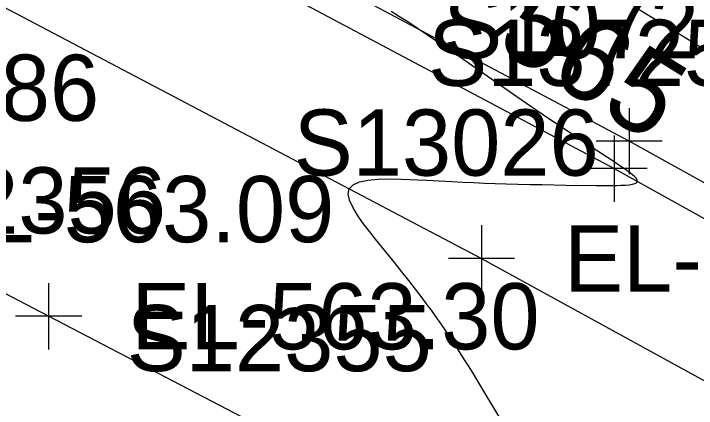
# Model space of a CAD drawing. Extents: x 1729869 to 1735532, y 648588 to 653771.
# Drawn here: x 1730620.93 to 1730662.21, y 652456.64 to 652480.48 of the extents above; entities that cross this region are included whole.
import ezdxf

# ---------------------------------------------------------------- set-up
doc = ezdxf.new("R2010")
doc.units = 0
for name, color, linetype in [('SURVEY - CONTOURS - Index with Text', 7, 'Continuous'), ('SURVEY - CONTOURS - Intermediate with optional Text', 7, 'Continuous'), ('SURVEY - DTM - Breaklines', 7, 'Continuous'), ('SURVEY - DTM - Breaklines - Points - Locators', 7, 'Continuous'), ('SURVEY - DTM - Breaklines - Points - Numbers', 7, 'Continuous'), ('SURVEY - TRANSPORTATION - Features', 7, 'Continuous'), ('SURVEY - TRANSPORTATION - Features - Points - Locators', 7, 'Continuous'), ('SURVEY - TRANSPORTATION - Features - Points - Numbers', 7, 'Continuous'), ('SURVEY - TRANSPORTATION - Roads', 7, 'Continuous'), ('SURVEY - TRANSPORTATION - Roads - Points - Elevations', 7, 'Continuous'), ('SURVEY - TRANSPORTATION - Roads - Points - Locators', 7, 'Continuous'), ('SURVEY - TRANSPORTATION - Roads - Points - Numbers', 7, 'Continuous')]:
    doc.layers.add(name, color=color, linetype=linetype)

msp = doc.modelspace()

# ---------------------------------------------------------------- linework, layer by layer
at = {"layer": 'SURVEY - CONTOURS - Intermediate with optional Text'}
for points in [[(1730662.688, 652478.32), (1730661.729, 652478.912), (1730660.479, 652479.674), (1730658.654, 652480.775)], [(1730652.709, 652452.13), (1730649.387, 652457.631), (1730648.728, 652458.714), (1730648.466, 652459.138), (1730648.201, 652459.563), (1730647.932, 652459.989), (1730647.659, 652460.415), (1730647.381, 652460.841), (1730647.06, 652461.322), (1730646.721, 652461.815), (1730646.547, 652462.063), (1730646.37, 652462.313), (1730646.189, 652462.564), (1730646.003, 652462.818), (1730645.626, 652463.321), (1730645.233, 652463.835), (1730644.826, 652464.358), (1730644.407, 652464.887), (1730643.978, 652465.422), (1730642.82, 652466.849), (1730642.467, 652467.293), (1730642.072, 652467.81), (1730641.719, 652468.311), (1730641.433, 652468.784), (1730641.238, 652469.215), (1730641.159, 652469.592), (1730641.22, 652469.902), (1730641.453, 652470.147), (1730641.84, 652470.316), (1730642.353, 652470.422), (1730642.963, 652470.477), (1730643.644, 652470.494), (1730644.368, 652470.484), (1730644.87, 652470.468), (1730645.377, 652470.448), (1730645.887, 652470.423), (1730647.426, 652470.341), (1730648.089, 652470.308), (1730648.748, 652470.278), (1730649.404, 652470.251), (1730650.056, 652470.227), (1730650.707, 652470.206), (1730651.42, 652470.185), (1730652.162, 652470.167), (1730652.895, 652470.152), (1730654.31, 652470.13), (1730656.161, 652470.108), (1730656.909, 652470.104), (1730657.402, 652470.108), (1730657.649, 652470.113), (1730657.912, 652470.125), (1730658.144, 652470.144), (1730658.34, 652470.172), (1730658.494, 652470.212), (1730658.598, 652470.266), (1730658.647, 652470.336), (1730658.639, 652470.419), (1730658.582, 652470.517), (1730658.481, 652470.628), (1730658.345, 652470.75), (1730658.178, 652470.881), (1730657.93, 652471.061), (1730657.652, 652471.253), (1730657.178, 652471.57), (1730655.476, 652472.685), (1730654.462, 652473.355), (1730653.416, 652474.054), (1730652.519, 652474.66), (1730651.625, 652475.271), (1730650.376, 652476.135), (1730647.478, 652478.152), (1730646.936, 652478.526), (1730646.408, 652478.889), (1730645.898, 652479.234), (1730645.415, 652479.557), (1730645.248, 652479.667), (1730644.762, 652479.983), (1730644.271, 652480.297), (1730643.764, 652480.617)]]:
    msp.add_lwpolyline(points, dxfattribs=at)
at = {"layer": 'SURVEY - DTM - Breaklines'}
msp.add_lwpolyline([(1730701.831, 652448.311), (1730680.069, 652460.611), (1730658.147, 652472.777), (1730635.92, 652484.613), (1730613.644, 652496.246), (1730591.357, 652507.57), (1730568.855, 652518.695), (1730546.07, 652529.531), (1730523.318, 652540.081), (1730500.602, 652550.622), (1730482.95, 652558.576)], dxfattribs=at)
at = {"layer": 'SURVEY - DTM - Breaklines - Points - Locators'}
for p, q in [((1730658.147, 652474.777), (1730658.147, 652470.777)), ((1730660.147, 652472.777), (1730656.147, 652472.777))]:
    msp.add_line(p, q, dxfattribs=at)
at = {"layer": 'SURVEY - TRANSPORTATION - Features'}
msp.add_lwpolyline([(1730482.128, 652556.778), (1730499.818, 652548.902), (1730522.526, 652538.364), (1730545.264, 652527.819), (1730568.012, 652517.002), (1730590.497, 652505.885), (1730612.785, 652494.561), (1730635.04, 652482.939), (1730657.237, 652471.119), (1730679.148, 652458.959), (1730700.909, 652446.658)], dxfattribs=at)
at = {"layer": 'SURVEY - TRANSPORTATION - Features - Points - Locators'}
for p, q in [((1730657.237, 652473.119), (1730657.237, 652469.119)), ((1730659.237, 652471.119), (1730655.237, 652471.119))]:
    msp.add_line(p, q, dxfattribs=at)
at = {"layer": 'SURVEY - TRANSPORTATION - Roads'}
for points in [[(1730477.741, 652549.555), (1730480.41, 652548.336), (1730500.427, 652539.207), (1730529.488, 652525.811), (1730560.256, 652511.345), (1730583.532, 652499.762), (1730613.819, 652484.316), (1730649.217, 652465.696), (1730673.763, 652452.23)], [(1730639.01, 652453.881), (1730623.049, 652462.2), (1730610.635, 652468.672), (1730596.418, 652476.006), (1730574.978, 652486.792), (1730557.081, 652495.716), (1730531.873, 652507.902), (1730522.838, 652512.189), (1730497.394, 652523.874), (1730478.726, 652532.248)]]:
    msp.add_lwpolyline(points, dxfattribs=at)
at = {"layer": 'SURVEY - TRANSPORTATION - Roads - Points - Locators'}
for p, q in [((1730649.217, 652467.696), (1730649.217, 652463.696)), ((1730651.217, 652465.696), (1730647.217, 652465.696)), ((1730623.049, 652464.2), (1730623.049, 652460.2)), ((1730625.049, 652462.2), (1730621.049, 652462.2))]:
    msp.add_line(p, q, dxfattribs=at)

# ---------------------------------------------------------------- texts
at = {"layer": 'SURVEY - CONTOURS - Index with Text'}
msp.add_text('565', height=5, rotation=328.2295, dxfattribs=at).set_placement((1730649.959, 652478.515))
at = {"layer": 'SURVEY - DTM - Breaklines - Points - Numbers'}
msp.add_text('S10727', height=4, dxfattribs=at).set_placement((1730646.907, 652477.777))
at = {"layer": 'SURVEY - TRANSPORTATION - Features - Points - Numbers'}
msp.add_text('S13725', height=4, dxfattribs=at).set_placement((1730645.997, 652476.119))
at = {"layer": 'SURVEY - TRANSPORTATION - Roads - Points - Elevations'}
for s, p in [('EL-562.86', (1730601.418, 652474.006)), ('EL-563.09', (1730615.635, 652466.672)), ('EL-564.15', (1730654.217, 652463.696)), ('EL-563.30', (1730628.049, 652460.2))]:
    msp.add_text(s, height=4, dxfattribs=at).set_placement(p)
at = {"layer": 'SURVEY - TRANSPORTATION - Roads - Points - Numbers'}
for s, p in [('S13026', (1730637.867, 652470.696)), ('S12356', (1730611.699, 652467.2)), ('S12355', (1730627.77, 652458.881))]:
    msp.add_text(s, height=4, dxfattribs=at).set_placement(p)

doc.saveas('drawing.dxf')
